(* Logix 5000 project; controller AMCI_3204_AOP_AOI_sample_RSLogix_V28 vendor 1 type 14 code 92 rev 28.11; software revision 28.00 *)

TASK MainTask (continuous, watchdog 500 ms) : MainProgram

MODULES
   Local : vendor 1 type 14 code 92 (ICP 0, rev 28.11)
      AMCI_3204 : vendor 10 type 100 code 33 (ICP 4, rev 1.1, Output RPI 5 ms)
           Local:4:O.Ch1.Data0   // AMCI 3204 channel 1 command word
           Local:4:O.Ch2.Data0   // AMCI 3204 channel 2 command word
           Local:4:O.Ch3.Data0   // AMCI 3204 channel 3 command word
           Local:4:O.Ch4.Data0   // AMCI 3204 channel 4 command word
END_MODULES

ADD_ON_INSTRUCTION AMCI_3204_AOP_Absolute_Move   (* revision 1.0, vendor AMCI, ExecuteEnableInFalse *)
VAR_INPUT
   axis_status_bits : INT; {required}
   channel_number : INT; {required}
   _0_normal_1_S_Curve_Acceleration : BOOL;
   _0_Triangular_1_Trapezoidal_S_Curve : BOOL;
   Target_Position : DINT; {required}
   Programmed_speed : DINT; {required}
   Acceleration : DINT; {required}
   Deceleration : DINT; {required}
END_VAR
VAR_IN_OUT
   AMCI_3204_output_data : AM:1756_3204:O:0; {required}
END_VAR
VAR_OUTPUT
   EN : BOOL; {access Read Only, visible}
   ER : BOOL; {access Read Only, visible}
END_VAR
VAR
   command_data_block : DINT[8]; {access None}
END_VAR

ROUTINE EnableInFalse   (* ladder *)
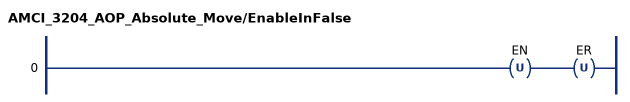
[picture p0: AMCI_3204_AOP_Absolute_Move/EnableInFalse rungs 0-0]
   0: OTU(EN)OTU(ER);
END_ROUTINE

ROUTINE Logic   (* ladder *)
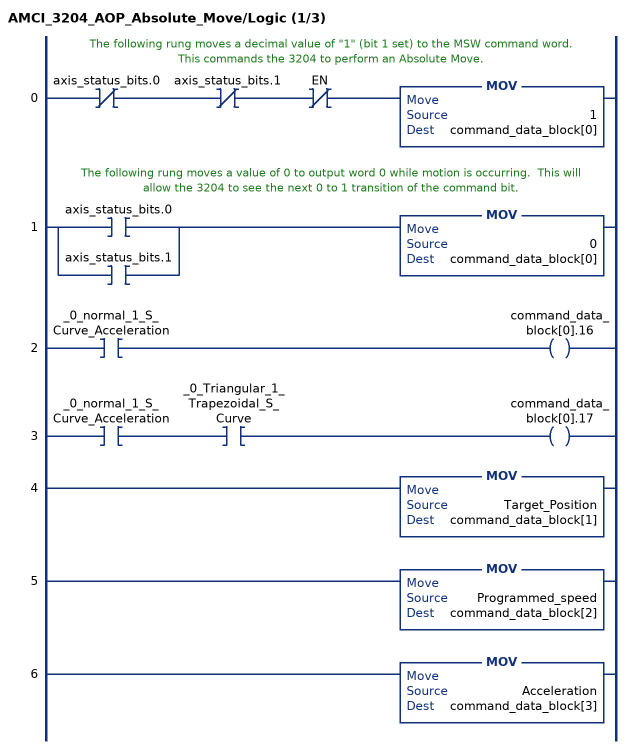
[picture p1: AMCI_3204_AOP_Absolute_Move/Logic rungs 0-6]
   // The following rung moves a decimal value of "1" (bit 1 set) to the MSW command word.  This commands the 3204 to perform an Absolute Move.
   0: XIO(axis_status_bits.0)XIO(axis_status_bits.1)XIO(EN)MOV(1,command_data_block[0]);
   // The following rung moves a value of 0 to output word 0 while motion is occurring.  This will allow the 3204 to see the next 0 to 1 transition of the command bit.
   1: [XIC(axis_status_bits.0) ,XIC(axis_status_bits.1) ]MOV(0,command_data_block[0]);
   2: XIC(_0_normal_1_S_Curve_Acceleration)OTE(command_data_block[0].16);
   3: XIC(_0_normal_1_S_Curve_Acceleration)XIC(_0_Triangular_1_Trapezoidal_S_Curve)OTE(command_data_block[0].17);
   4: MOV(Target_Position,command_data_block[1]);
   5: MOV(Programmed_speed,command_data_block[2]);
   6: MOV(Acceleration,command_data_block[3]);
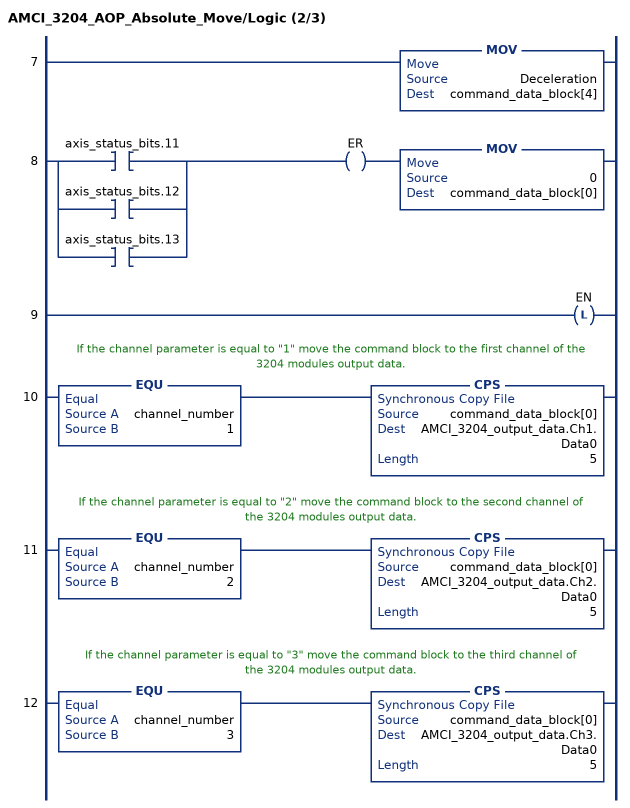
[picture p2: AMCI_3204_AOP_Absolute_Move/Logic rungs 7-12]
   7: MOV(Deceleration,command_data_block[4]);
   8: [XIC(axis_status_bits.11) ,XIC(axis_status_bits.12) ,XIC(axis_status_bits.13) ]OTE(ER)MOV(0,command_data_block[0]);
   9: OTL(EN);
   // If the channel parameter is equal to "1" move the command block to the first channel of the 3204 modules output data.
   10: EQU(channel_number,1)CPS(command_data_block[0],AMCI_3204_output_data.Ch1.Data0,5);
   // If the channel parameter is equal to "2" move the command block to the second channel of the 3204 modules output data.
   11: EQU(channel_number,2)CPS(command_data_block[0],AMCI_3204_output_data.Ch2.Data0,5);
   // If the channel parameter is equal to "3" move the command block to the third channel of the 3204 modules output data.
   12: EQU(channel_number,3)CPS(command_data_block[0],AMCI_3204_output_data.Ch3.Data0,5);
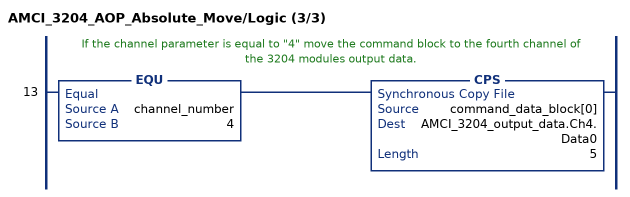
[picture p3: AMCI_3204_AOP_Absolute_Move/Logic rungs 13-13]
   // If the channel parameter is equal to "4" move the command block to the fourth channel of the 3204 modules output data.
   13: EQU(channel_number,4)CPS(command_data_block[0],AMCI_3204_output_data.Ch4.Data0,5);
END_ROUTINE
END_ADD_ON_INSTRUCTION

ADD_ON_INSTRUCTION AMCI_3204_AOP_Configure   (* revision 1.0 *)
VAR_INPUT
   channel_number : INT; {required}
   home_input : BOOL; {required}
   home_input_active_state : BOOL; {required}
   Emergency_Stop : BOOL; {required}
   Emergency_Stop_active_state : BOOL; {required}
   CW_Limit : BOOL; {required}
   CW_Limit_actitve_state : BOOL; {required}
   CCW_Limit : BOOL; {required}
   CCW_Limit_active_state : BOOL; {required}
   Backplane_Home_Proximity_Enable : BOOL;
   _0_CW_CCW_1_step_direction : BOOL; {required}
   _0_enable_1_disable_channel : BOOL;
   Starting_Speed : DINT; {required}
END_VAR
VAR_IN_OUT
   AMCi_3204_output_data : AM:1756_3204:O:0; {required}
END_VAR
VAR
   command_data_block : DINT[5];
        [0].31   // Mode Bit 1=Configuraiton Mode 0=Command Mode
END_VAR

ROUTINE Logic   (* ladder *)
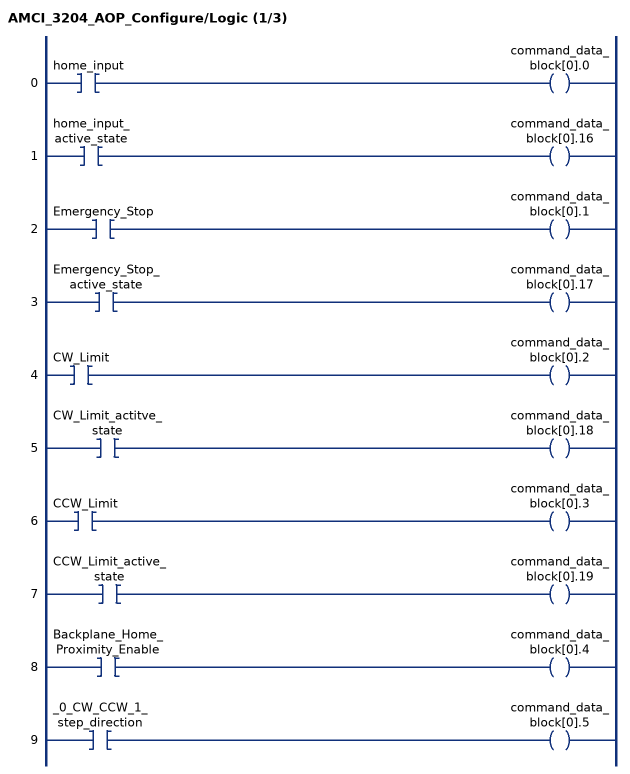
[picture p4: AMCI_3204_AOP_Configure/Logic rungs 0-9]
   0: XIC(home_input)OTE(command_data_block[0].0);
   1: XIC(home_input_active_state)OTE(command_data_block[0].16);
   2: XIC(Emergency_Stop)OTE(command_data_block[0].1);
   3: XIC(Emergency_Stop_active_state)OTE(command_data_block[0].17);
   4: XIC(CW_Limit)OTE(command_data_block[0].2);
   5: XIC(CW_Limit_actitve_state)OTE(command_data_block[0].18);
   6: XIC(CCW_Limit)OTE(command_data_block[0].3);
   7: XIC(CCW_Limit_active_state)OTE(command_data_block[0].19);
   8: XIC(Backplane_Home_Proximity_Enable)OTE(command_data_block[0].4);
   9: XIC(_0_CW_CCW_1_step_direction)OTE(command_data_block[0].5);
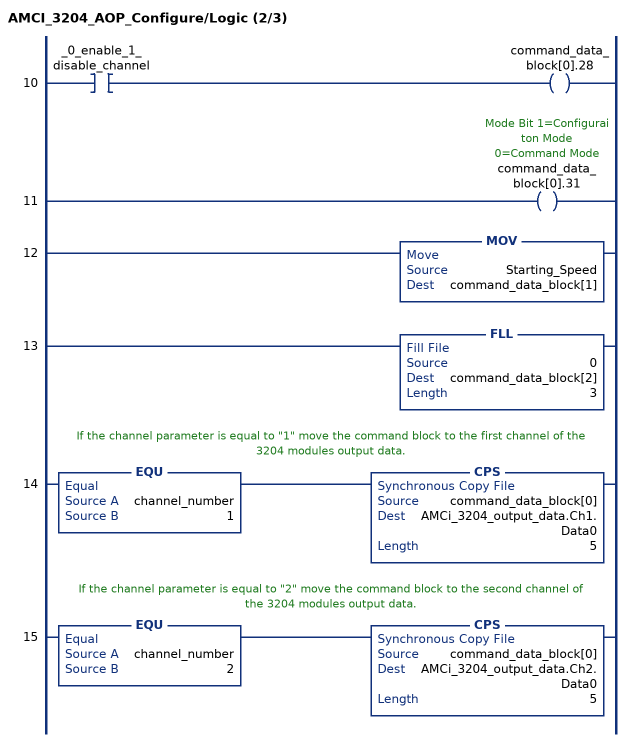
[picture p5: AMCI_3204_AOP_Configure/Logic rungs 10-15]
   10: XIC(_0_enable_1_disable_channel)OTE(command_data_block[0].28);
   11: OTE(command_data_block[0].31);
   12: MOV(Starting_Speed,command_data_block[1]);
   13: FLL(0,command_data_block[2],3);
   // If the channel parameter is equal to "1" move the command block to the first channel of the 3204 modules output data.
   14: EQU(channel_number,1)CPS(command_data_block[0],AMCi_3204_output_data.Ch1.Data0,5);
   // If the channel parameter is equal to "2" move the command block to the second channel of the 3204 modules output data.
   15: EQU(channel_number,2)CPS(command_data_block[0],AMCi_3204_output_data.Ch2.Data0,5);
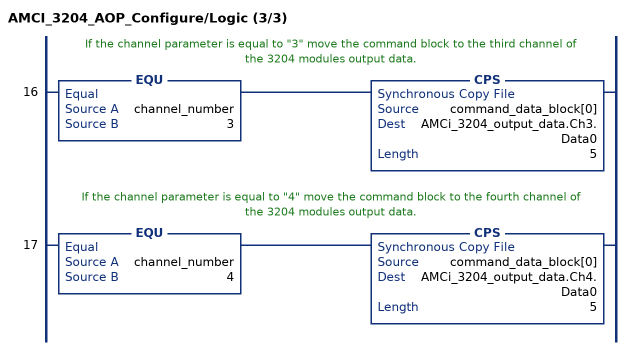
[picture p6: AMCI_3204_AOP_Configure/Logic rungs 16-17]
   // If the channel parameter is equal to "3" move the command block to the third channel of the 3204 modules output data.
   16: EQU(channel_number,3)CPS(command_data_block[0],AMCi_3204_output_data.Ch3.Data0,5);
   // If the channel parameter is equal to "4" move the command block to the fourth channel of the 3204 modules output data.
   17: EQU(channel_number,4)CPS(command_data_block[0],AMCi_3204_output_data.Ch4.Data0,5);
END_ROUTINE
END_ADD_ON_INSTRUCTION

ADD_ON_INSTRUCTION AMCI_3204_AOP_Hold   (* revision 1.0, vendor AMCI, ExecuteEnableInFalse *)
VAR_INPUT
   channel_number : INT; {required}
END_VAR
VAR_IN_OUT
   AMCI_3204_output_data : AM:1756_3204:O:0; {required}
END_VAR
VAR
   command_data_block : DINT[8]; {access None}
END_VAR

ROUTINE EnableInFalse   (* ladder *)
END_ROUTINE

ROUTINE Logic   (* ladder *)
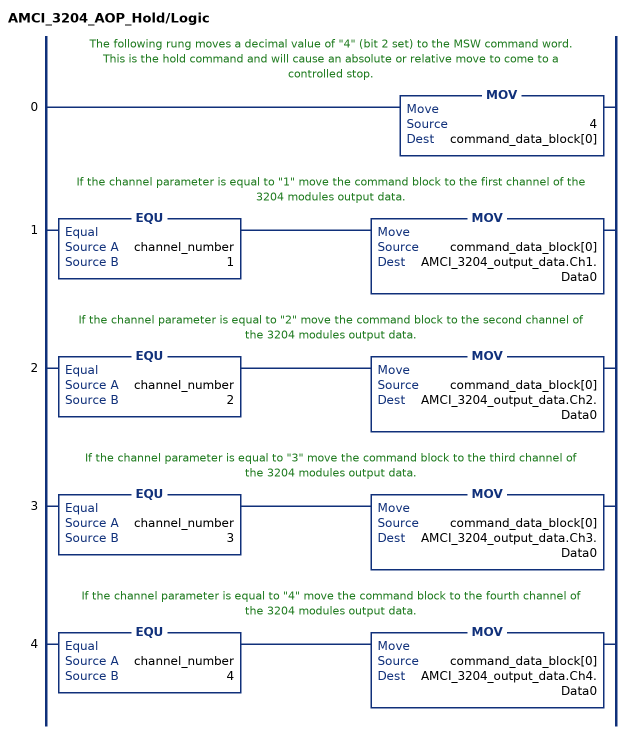
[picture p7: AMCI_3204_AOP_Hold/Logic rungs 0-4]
   // The following rung moves a decimal value of "4" (bit 2 set) to the MSW command word.  This is the hold command and will cause an absolute or relative move to come to a controlled stop.
   0: MOV(4,command_data_block[0]);
   // If the channel parameter is equal to "1" move the command block to the first channel of the 3204 modules output data.
   1: EQU(channel_number,1)MOV(command_data_block[0],AMCI_3204_output_data.Ch1.Data0);
   // If the channel parameter is equal to "2" move the command block to the second channel of the 3204 modules output data.
   2: EQU(channel_number,2)MOV(command_data_block[0],AMCI_3204_output_data.Ch2.Data0);
   // If the channel parameter is equal to "3" move the command block to the third channel of the 3204 modules output data.
   3: EQU(channel_number,3)MOV(command_data_block[0],AMCI_3204_output_data.Ch3.Data0);
   // If the channel parameter is equal to "4" move the command block to the fourth channel of the 3204 modules output data.
   4: EQU(channel_number,4)MOV(command_data_block[0],AMCI_3204_output_data.Ch4.Data0);
END_ROUTINE
END_ADD_ON_INSTRUCTION

ADD_ON_INSTRUCTION AMCI_3204_AOP_Home_CCW   (* revision 1.0, vendor AMCI, ExecuteEnableInFalse *)
VAR_INPUT
   axis_status_bits : INT; {required}
   channel_number : INT; {required}
   Programmed_speed : DINT; {required}
   Acceleration : DINT; {required}
   Deceleration : DINT; {required}
END_VAR
VAR_IN_OUT
   AMCI_3204_output_data : AM:1756_3204:O:0; {required}
END_VAR
VAR_OUTPUT
   EN : BOOL; {access Read Only, visible}
   ER : BOOL; {access Read Only, visible}
END_VAR
VAR
   command_data_block : DINT[8]; {access None}
END_VAR

ROUTINE EnableInFalse   (* ladder *)
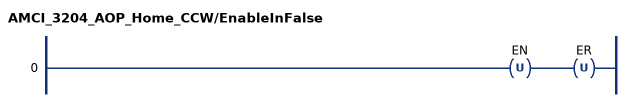
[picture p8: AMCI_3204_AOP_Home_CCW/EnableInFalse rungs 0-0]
   0: OTU(EN)OTU(ER);
END_ROUTINE

ROUTINE Logic   (* ladder *)
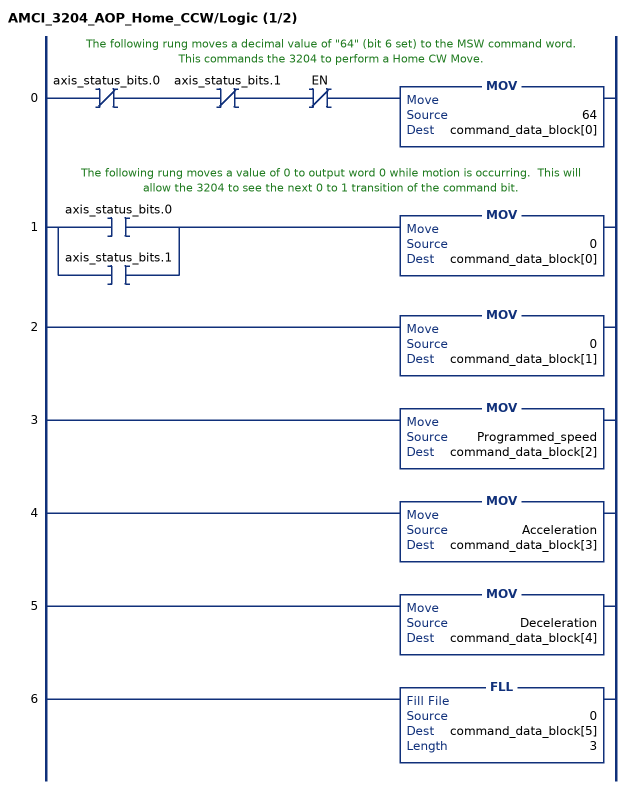
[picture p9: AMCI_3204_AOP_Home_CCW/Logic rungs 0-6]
   // The following rung moves a decimal value of "64" (bit 6 set) to the MSW command word.  This commands the 3204 to perform a Home CW Move.
   0: XIO(axis_status_bits.0)XIO(axis_status_bits.1)XIO(EN)MOV(64,command_data_block[0]);
   // The following rung moves a value of 0 to output word 0 while motion is occurring.  This will allow the 3204 to see the next 0 to 1 transition of the command bit.
   1: [XIC(axis_status_bits.0) ,XIC(axis_status_bits.1) ]MOV(0,command_data_block[0]);
   2: MOV(0,command_data_block[1]);
   3: MOV(Programmed_speed,command_data_block[2]);
   4: MOV(Acceleration,command_data_block[3]);
   5: MOV(Deceleration,command_data_block[4]);
   6: FLL(0,command_data_block[5],3);
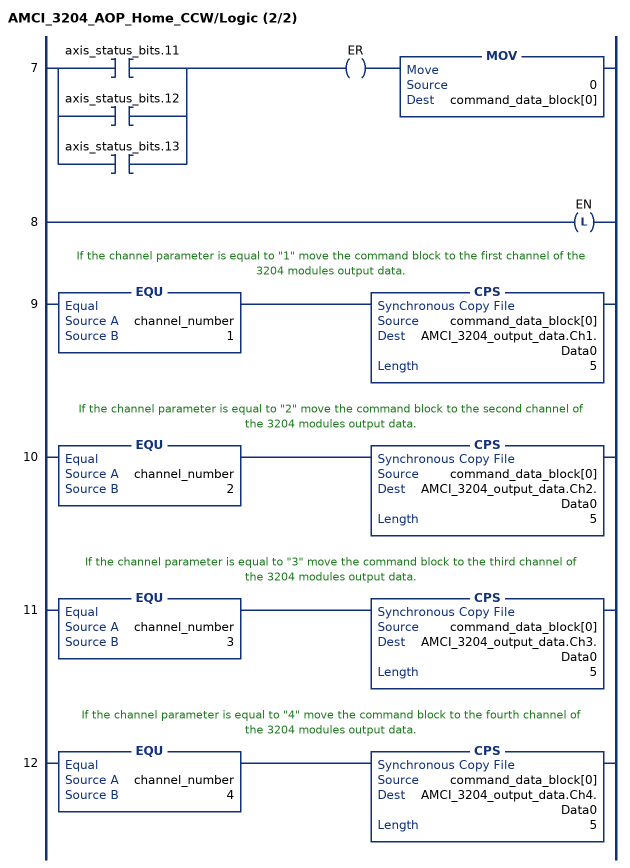
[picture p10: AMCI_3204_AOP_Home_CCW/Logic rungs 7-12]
   7: [XIC(axis_status_bits.11) ,XIC(axis_status_bits.12) ,XIC(axis_status_bits.13) ]OTE(ER)MOV(0,command_data_block[0]);
   8: OTL(EN);
   // If the channel parameter is equal to "1" move the command block to the first channel of the 3204 modules output data.
   9: EQU(channel_number,1)CPS(command_data_block[0],AMCI_3204_output_data.Ch1.Data0,5);
   // If the channel parameter is equal to "2" move the command block to the second channel of the 3204 modules output data.
   10: EQU(channel_number,2)CPS(command_data_block[0],AMCI_3204_output_data.Ch2.Data0,5);
   // If the channel parameter is equal to "3" move the command block to the third channel of the 3204 modules output data.
   11: EQU(channel_number,3)CPS(command_data_block[0],AMCI_3204_output_data.Ch3.Data0,5);
   // If the channel parameter is equal to "4" move the command block to the fourth channel of the 3204 modules output data.
   12: EQU(channel_number,4)CPS(command_data_block[0],AMCI_3204_output_data.Ch4.Data0,5);
END_ROUTINE
END_ADD_ON_INSTRUCTION

ADD_ON_INSTRUCTION AMCI_3204_AOP_Home_CW   (* revision 1.0, vendor AMCI, ExecuteEnableInFalse *)
VAR_INPUT
   axis_status_bits : INT; {required}
   channel_number : INT; {required}
   Programmed_speed : DINT; {required}
   Acceleration : DINT; {required}
   Deceleration : DINT; {required}
END_VAR
VAR_IN_OUT
   AMCI_3204_output_data : AM:1756_3204:O:0; {required}
END_VAR
VAR_OUTPUT
   EN : BOOL; {access Read Only, visible}
   ER : BOOL; {access Read Only, visible}
END_VAR
VAR
   command_data_block : DINT[8]; {access None}
END_VAR

ROUTINE EnableInFalse   (* ladder *)
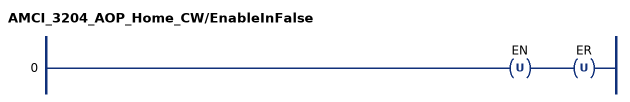
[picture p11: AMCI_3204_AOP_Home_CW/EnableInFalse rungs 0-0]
   0: OTU(EN)OTU(ER);
END_ROUTINE

ROUTINE Logic   (* ladder *)
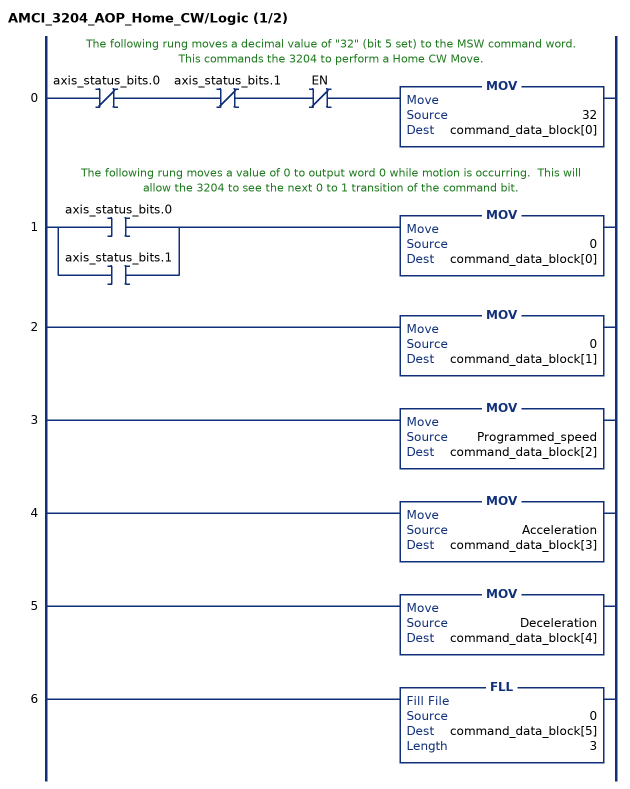
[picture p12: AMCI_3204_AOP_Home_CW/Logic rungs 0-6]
   // The following rung moves a decimal value of "32" (bit 5 set) to the MSW command word.  This commands the 3204 to perform a Home CW Move.
   0: XIO(axis_status_bits.0)XIO(axis_status_bits.1)XIO(EN)MOV(32,command_data_block[0]);
   // The following rung moves a value of 0 to output word 0 while motion is occurring.  This will allow the 3204 to see the next 0 to 1 transition of the command bit.
   1: [XIC(axis_status_bits.0) ,XIC(axis_status_bits.1) ]MOV(0,command_data_block[0]);
   2: MOV(0,command_data_block[1]);
   3: MOV(Programmed_speed,command_data_block[2]);
   4: MOV(Acceleration,command_data_block[3]);
   5: MOV(Deceleration,command_data_block[4]);
   6: FLL(0,command_data_block[5],3);
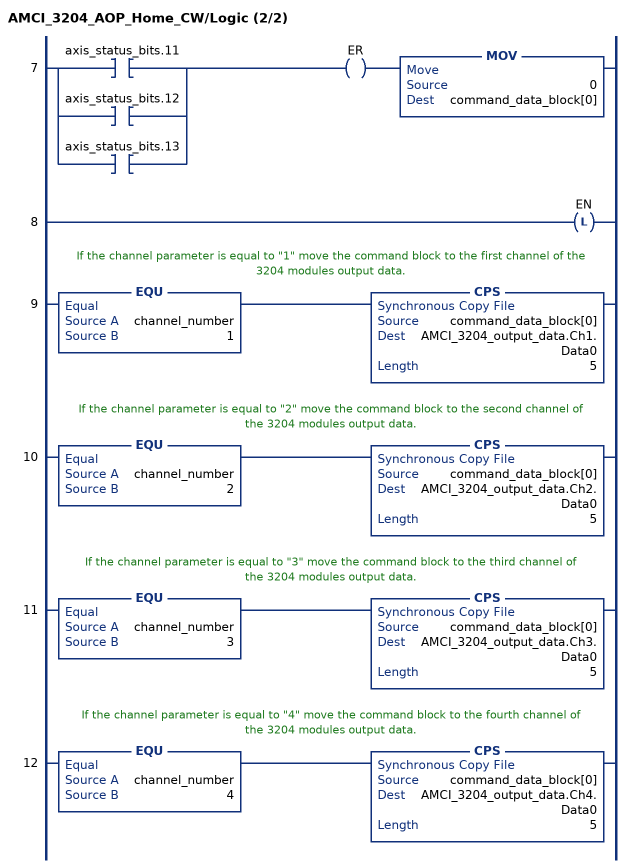
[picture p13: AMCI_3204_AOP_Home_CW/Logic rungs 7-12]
   7: [XIC(axis_status_bits.11) ,XIC(axis_status_bits.12) ,XIC(axis_status_bits.13) ]OTE(ER)MOV(0,command_data_block[0]);
   8: OTL(EN);
   // If the channel parameter is equal to "1" move the command block to the first channel of the 3204 modules output data.
   9: EQU(channel_number,1)CPS(command_data_block[0],AMCI_3204_output_data.Ch1.Data0,5);
   // If the channel parameter is equal to "2" move the command block to the second channel of the 3204 modules output data.
   10: EQU(channel_number,2)CPS(command_data_block[0],AMCI_3204_output_data.Ch2.Data0,5);
   // If the channel parameter is equal to "3" move the command block to the third channel of the 3204 modules output data.
   11: EQU(channel_number,3)CPS(command_data_block[0],AMCI_3204_output_data.Ch3.Data0,5);
   // If the channel parameter is equal to "4" move the command block to the fourth channel of the 3204 modules output data.
   12: EQU(channel_number,4)CPS(command_data_block[0],AMCI_3204_output_data.Ch4.Data0,5);
END_ROUTINE
END_ADD_ON_INSTRUCTION

ADD_ON_INSTRUCTION AMCI_3204_AOP_Immediate_Stop   (* revision 1.0, vendor AMCI, ExecuteEnableInFalse *)
VAR_INPUT
   channel_number : INT; {required}
END_VAR
VAR_IN_OUT
   AMCI_3204_output_data : AM:1756_3204:O:0; {required}
END_VAR
VAR
   command_data_block : DINT[8]; {access None}
END_VAR

ROUTINE EnableInFalse   (* ladder *)
END_ROUTINE

ROUTINE Logic   (* ladder *)
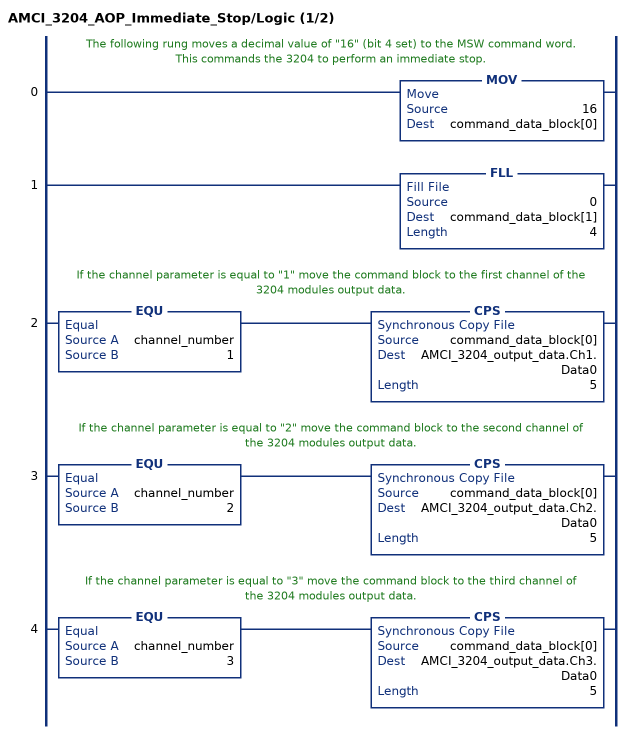
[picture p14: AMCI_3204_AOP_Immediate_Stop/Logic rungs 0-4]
   // The following rung moves a decimal value of "16" (bit 4 set) to the MSW command word.  This commands the 3204 to perform an immediate stop.
   0: MOV(16,command_data_block[0]);
   1: FLL(0,command_data_block[1],4);
   // If the channel parameter is equal to "1" move the command block to the first channel of the 3204 modules output data.
   2: EQU(channel_number,1)CPS(command_data_block[0],AMCI_3204_output_data.Ch1.Data0,5);
   // If the channel parameter is equal to "2" move the command block to the second channel of the 3204 modules output data.
   3: EQU(channel_number,2)CPS(command_data_block[0],AMCI_3204_output_data.Ch2.Data0,5);
   // If the channel parameter is equal to "3" move the command block to the third channel of the 3204 modules output data.
   4: EQU(channel_number,3)CPS(command_data_block[0],AMCI_3204_output_data.Ch3.Data0,5);
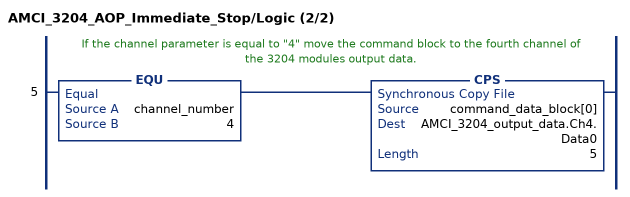
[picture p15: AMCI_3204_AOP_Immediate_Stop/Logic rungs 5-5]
   // If the channel parameter is equal to "4" move the command block to the fourth channel of the 3204 modules output data.
   5: EQU(channel_number,4)CPS(command_data_block[0],AMCI_3204_output_data.Ch4.Data0,5);
END_ROUTINE
END_ADD_ON_INSTRUCTION

ADD_ON_INSTRUCTION AMCI_3204_AOP_Manual_Move_CCW   (* revision 1.0, vendor AMCI, ExecuteEnableInFalse *)
VAR_INPUT
   axis_status_bits : INT; {required}
   channel_number : INT; {required}
   _0_normal_1_S_Curve_Acceleration : BOOL;
   _0_Triangular_1_Trapezoidal_S_Curve : BOOL;
   Programmed_speed : DINT; {required}
   Acceleration : DINT; {required}
   Deceleration : DINT; {required}
END_VAR
VAR_IN_OUT
   AMCI_3204_output_data : AM:1756_3204:O:0; {required}
END_VAR
VAR_OUTPUT
   EN : BOOL; {access Read Only, visible}
   Manual_Move_CCW_occurring : BOOL; {access Read Only, visible}
   ER : BOOL; {access Read Only, visible}
END_VAR
VAR
   command_data_block : DINT[8]; {access None}
END_VAR

ROUTINE EnableInFalse   (* ladder *)
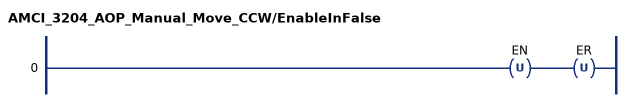
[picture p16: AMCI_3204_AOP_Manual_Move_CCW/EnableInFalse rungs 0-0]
   0: OTU(EN)OTU(ER);
END_ROUTINE

ROUTINE Logic   (* ladder *)
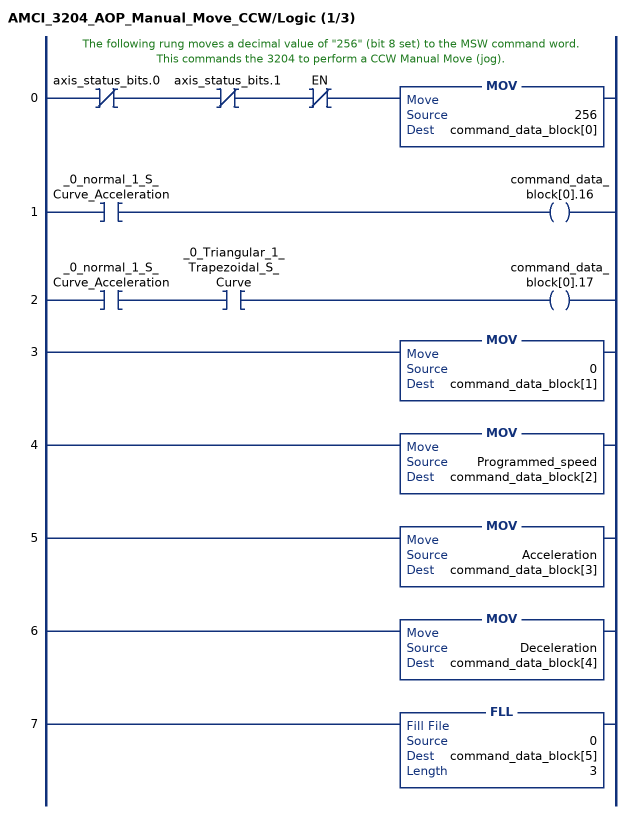
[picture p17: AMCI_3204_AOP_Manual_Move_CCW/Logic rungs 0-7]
   // The following rung moves a decimal value of "256" (bit 8 set) to the MSW command word.  This commands the 3204 to perform a CCW Manual Move (jog).
   0: XIO(axis_status_bits.0)XIO(axis_status_bits.1)XIO(EN)MOV(256,command_data_block[0]);
   1: XIC(_0_normal_1_S_Curve_Acceleration)OTE(command_data_block[0].16);
   2: XIC(_0_normal_1_S_Curve_Acceleration)XIC(_0_Triangular_1_Trapezoidal_S_Curve)OTE(command_data_block[0].17);
   3: MOV(0,command_data_block[1]);
   4: MOV(Programmed_speed,command_data_block[2]);
   5: MOV(Acceleration,command_data_block[3]);
   6: MOV(Deceleration,command_data_block[4]);
   7: FLL(0,command_data_block[5],3);
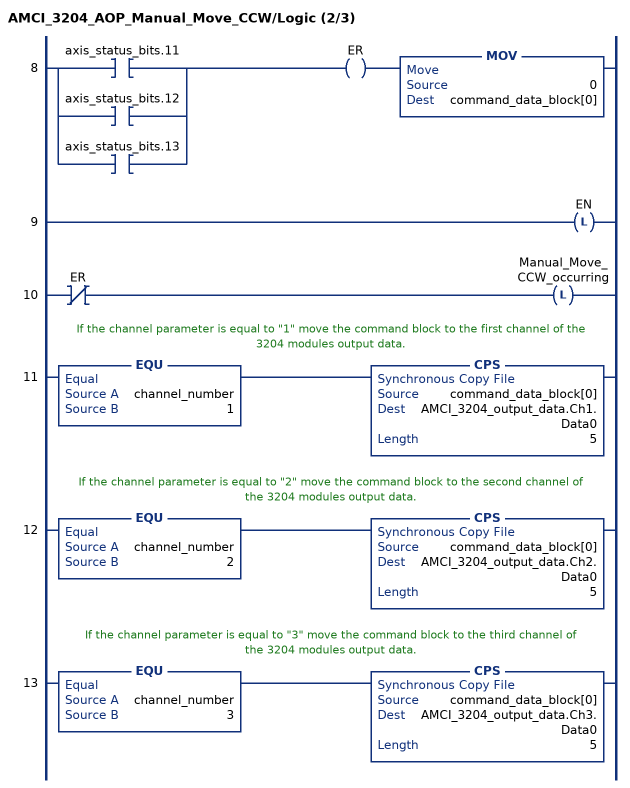
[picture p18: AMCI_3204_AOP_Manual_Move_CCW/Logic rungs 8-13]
   8: [XIC(axis_status_bits.11) ,XIC(axis_status_bits.12) ,XIC(axis_status_bits.13) ]OTE(ER)MOV(0,command_data_block[0]);
   9: OTL(EN);
   10: XIO(ER)OTL(Manual_Move_CCW_occurring);
   // If the channel parameter is equal to "1" move the command block to the first channel of the 3204 modules output data.
   11: EQU(channel_number,1)CPS(command_data_block[0],AMCI_3204_output_data.Ch1.Data0,5);
   // If the channel parameter is equal to "2" move the command block to the second channel of the 3204 modules output data.
   12: EQU(channel_number,2)CPS(command_data_block[0],AMCI_3204_output_data.Ch2.Data0,5);
   // If the channel parameter is equal to "3" move the command block to the third channel of the 3204 modules output data.
   13: EQU(channel_number,3)CPS(command_data_block[0],AMCI_3204_output_data.Ch3.Data0,5);
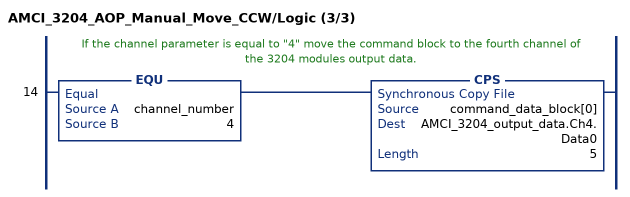
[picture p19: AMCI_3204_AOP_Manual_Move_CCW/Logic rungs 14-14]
   // If the channel parameter is equal to "4" move the command block to the fourth channel of the 3204 modules output data.
   14: EQU(channel_number,4)CPS(command_data_block[0],AMCI_3204_output_data.Ch4.Data0,5);
END_ROUTINE
END_ADD_ON_INSTRUCTION
